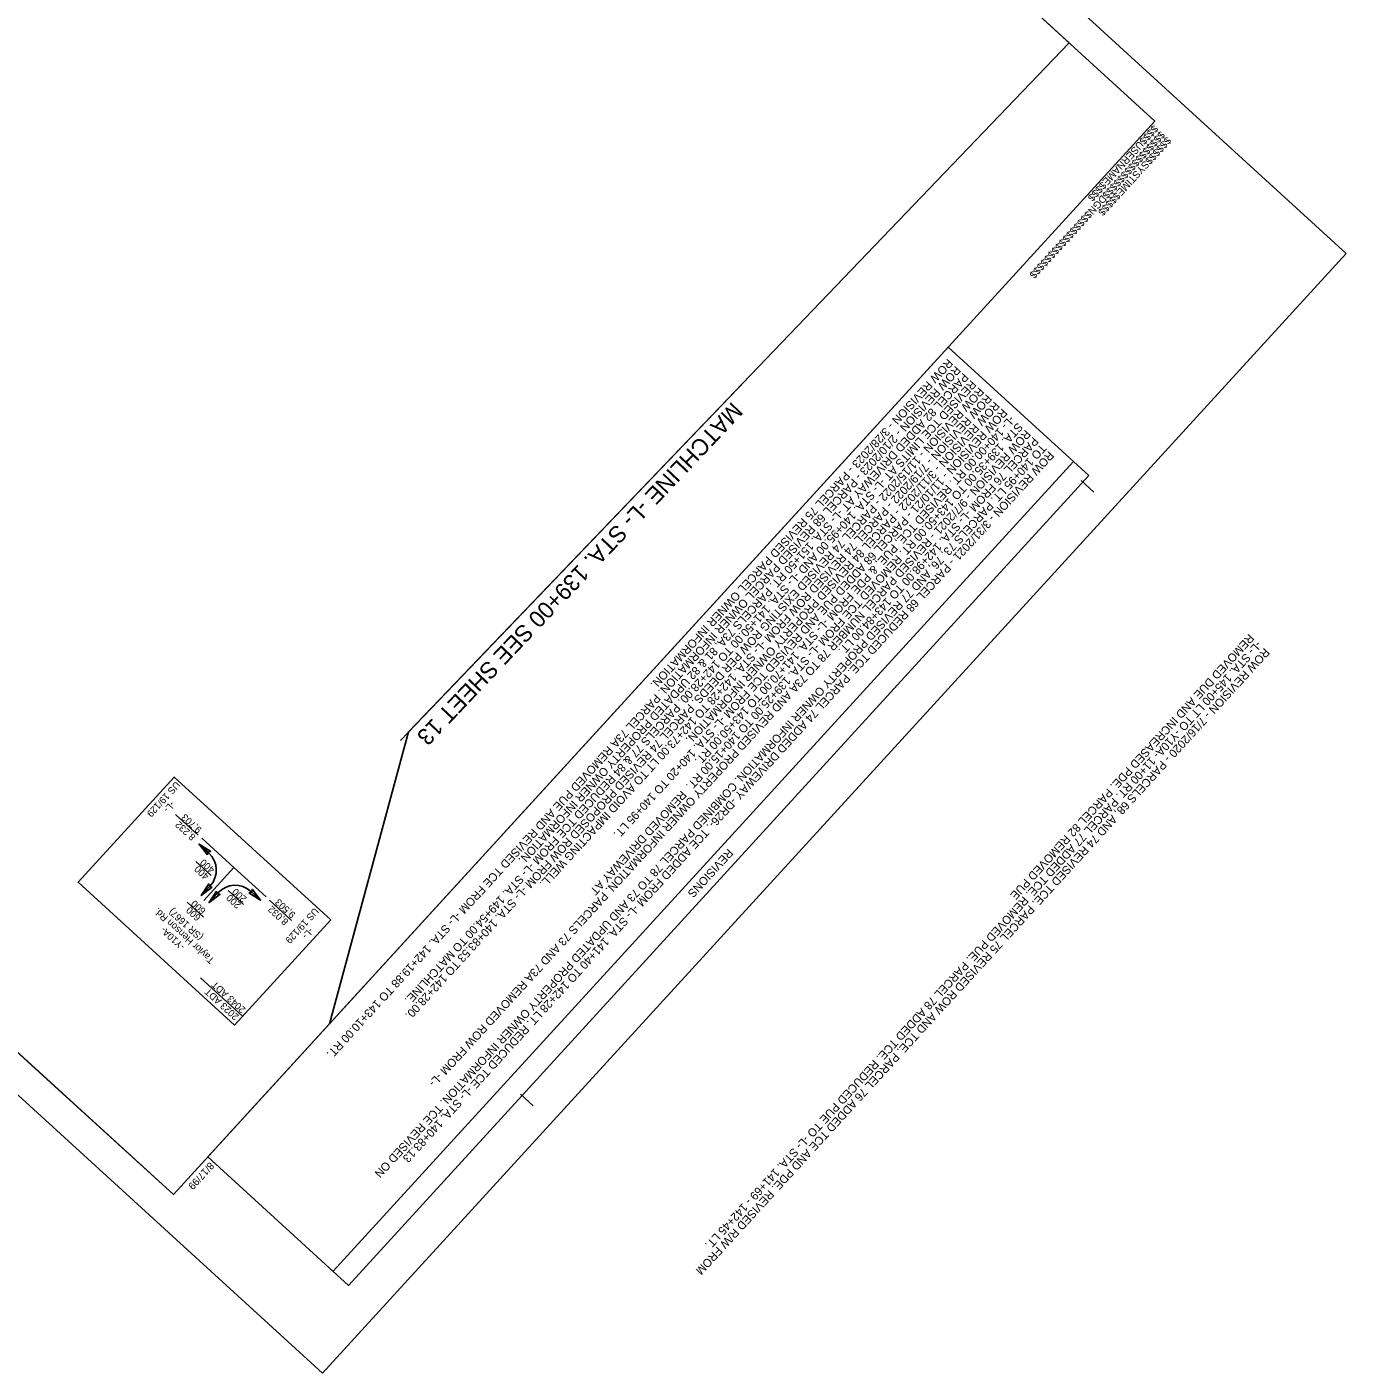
# Model space of a CAD drawing. Extents: x 475722 to 477703, y 499689 to 501633.
# Drawn here: x 476751 to 477703, y 499689 to 500661 of the extents above; entities that cross this region are included whole.
import ezdxf

# ---------------------------------------------------------------- set-up
doc = ezdxf.new("R2010")
doc.units = 0
for name, color, linetype in [('Matchline', 7, 'Continuous'), ('Matchline Text', 7, 'Continuous'), ('Prop DSN Text', 7, 'Continuous'), ('Prop Grid Mask', 7, 'Continuous'), ('Prop PHM Traffic Signal CELL', 7, 'Continuous'), ('Sheet Block Revision CELL', 7, 'Continuous'), ('Sheet Clip Boundary CELL', 7, 'Continuous'), ('Sheet Plan CELL', 7, 'Continuous'), ('Sheet Plot Border Outside CELL', 7, 'Continuous')]:
    doc.layers.add(name, color=color, linetype=linetype)

msp = doc.modelspace()

# ---------------------------------------------------------------- linework, layer by layer
at = {"layer": 'Matchline'}
msp.add_line((477269.58, 500406.16), (477020.46, 500146.28), dxfattribs=at)
at = {"layer": 'Prop DSN Text'}
for p, q in [((476878.68, 500030.7), (476900.34, 500054.4)), ((476876.81, 500034.23), (476883.24, 500041.25)), ((476882.34, 500029.15), (476888.77, 500036.18))]:
    msp.add_line(p, q, dxfattribs=at)
for points in [[(476881.33, 500063.57), (476875.17, 500071.39), (476883.62, 500066.07), (476881.49, 500065.6)], [(476884.63, 500040.39), (476876.81, 500034.23), (476882.13, 500042.68), (476882.6, 500040.55)], [(476911.17, 500036.29), (476919.52, 500030.86), (476913.46, 500038.8), (476913.18, 500036.64)], [(476887.79, 500037.5), (476882.36, 500029.15), (476890.3, 500035.21), (476888.14, 500035.49)]]:
    msp.add_lwpolyline(points, close=True, dxfattribs=at)
for centre, start, end in [((476870.87, 500052.58), 317.53481, 47.53479), ((476901.17, 500024.89), 47.62497, 137.62496)]:
    msp.add_arc(centre, 16.77, start, end, dxfattribs=at)
at = {"layer": 'Prop Grid Mask'}
msp.add_lwpolyline([(476900.81, 499940.64), (476787.89, 500043.82), (476857.32, 500119.8), (476970.24, 500016.62)], close=True, dxfattribs=at)
at = {"layer": 'Prop PHM Traffic Signal CELL'}
for p, q in [((476858.2, 500092.71), (476874.54, 500077.78)), ((476882.13, 500065.01), (476875.1, 500071.44)), ((476877.13, 500075.61), (476900.34, 500054.4)), ((476872.83, 500058.94), (476884.01, 500048.73)), ((476923.55, 500033.2), (476900.34, 500054.4)), ((476866.56, 500029.43), (476878.44, 500018.57)), ((476907.18, 500027.88), (476896.15, 500037.95)), ((476919.51, 500030.85), (476912.48, 500037.28)), ((476941.96, 500016.29), (476925.94, 500030.92)), ((476876.25, 499974.73), (476906.41, 499947.17))]:
    msp.add_line(p, q, dxfattribs=at)
at = {"layer": 'Sheet Block Revision CELL'}
msp.add_line((477506.17, 500347.75), (476971.88, 499763.02), dxfattribs=at)
msp.add_lwpolyline([(477517.42, 500337.46), (476983.13, 499752.76), (476881.48, 499845.57), (477415.77, 500430.27)], close=True, dxfattribs=at)
at = {"layer": 'Sheet Clip Boundary CELL'}
msp.add_lwpolyline([(475896.94, 500695.24), (476776.38, 499891.66), (476856.61, 499818.34), (476969.21, 499941.58), (477026.31, 500152.38), (477503.19, 500649.86), (476731.13, 501355.34), (476672.99, 501291.71), (476544.91, 501408.73), (475869.73, 500955.21), (476014.01, 500823.37)], close=True, dxfattribs=at)
at = {"layer": 'Sheet Plan CELL'}
for p, q in [((477564.89, 500593.48), (477564.89, 500593.48)), ((477521.05, 500325.38), (477511.83, 500333.83)), ((477116.34, 499882.45), (477107.08, 499890.87)), ((476856.61, 499818.34), (476856.61, 499818.34))]:
    msp.add_line(p, q, dxfattribs=at)
msp.add_lwpolyline([(475749.25, 500830.21), (476856.61, 499818.34), (477564.89, 500593.48), (476457.56, 501605.32)], close=True, dxfattribs=at)
at = {"layer": 'Sheet Plot Border Outside CELL'}
msp.add_lwpolyline([(477702.99, 500497.79), (476460.19, 501633.41), (475721.55, 500825.06), (476964.34, 499689.44)], close=True, dxfattribs=at)

# ---------------------------------------------------------------- texts
at = {"layer": 'Matchline Text'}
msp.add_text('MATCHLINE -L- STA. 139+00 SEE SHEET 13', height=12, rotation=226.58871, dxfattribs=at).set_placement((477259.86, 500391.23))
at = {"layer": 'Prop PHM Traffic Signal CELL'}
for s, rotation, p in [('US 19/129', 227.57996, (476858.36, 500117.07)), ('-L-', 227.57996, (476854.7, 500102.78)), ('8,232', 137.57984, (476873.13, 500077.09)), ('9,703', 137.57984, (476877.51, 500082.35)), ('400', 137.57984, (476886.9, 500053.5)), ('400', 137.57984, (476882.82, 500048.76)), ('200', 137.57993, (476910.07, 500032.37)), ('600', 137.57984, (476880.44, 500023.82)), ('200', 137.57993, (476905.88, 500027.98)), ('9,503', 137.57993, (476945.17, 500021.02)), ('Taylor Henson Rd. ', 137.57984, (476886.63, 499988.12)), ('(SR 1667)', 137.57984, (476878.52, 500004.92)), ('600', 137.57984, (476876.86, 500019.04)), ('8,032', 137.57993, (476940.12, 500015.92)), ('US 19/129', 227.57996, (476958.43, 500025.77)), ('-Y10A-', 137.57984, (476865.39, 499998.13)), ('-L-', 227.57996, (476954.76, 500011.48)), ('2043 ADT', 137.57984, (476909.19, 499952.49)), ('2023 ADT', 137.57984, (476904.28, 499947.39))]:
    msp.add_text(s, height=5, rotation=rotation, dxfattribs=at).set_placement(p)
at = {"layer": 'Sheet Block Revision CELL'}
for s, p in [('ROW REVISION - 3/28/2023 - PARCEL 75 REVISED PARCEL OWNER INFORMATION. ', (477415.4, 500422.28)), ('ROW REVISION - 2/10/2023 - PARCEL 68 REVISED PARCEL OWNER INFORMATION. PARCEL 73A REMOVED PUE AND REVISED TCE FROM -L- STA. 142+19.88 TO 143+10.00 RT. ', (477421.01, 500417.15)), ('PARCEL 82 ADDED DRIVEWAY AT -L- STA. 151+50 RT. PARCELS 73A, 81 & 82 UPDATED PROPERTY OWNER INFORMATION. ', (477426.63, 500412.02)), ('REVISED TCE LIMITS AT -L- STA. 140+95.00 AND -L- STA. 141+50.00 TO 142+28.00. PARCELS 77 & 84 REDUCED TCE FROM -L- STA. 149+54.00 TO MATCHLINE. ', (477432.24, 500406.89)), ('ROW REVISION - 11/15/2022 - PARCEL 74 REVISED EXISTING ROW PER DEEDS. PARCEL 74 REVISED PROPOSED ROW FROM -L- STA. 140+83.53 TO 142+28.00. ', (477437.86, 500401.76)), ('ROW REVISION - 7/19/2022 - PARCEL 74 REVISED ROW FROM -L- STA. 142+28 TO 142+73.00 LT TO AVOID IMPACTING WELL. ', (477443.47, 500396.63)), ('ROW REVISION - 3/11/2022 - PARCEL 84 REVISED PROPERTY OWNER INFORMATION.', (477449.09, 500391.5)), ('ROW REVISION - 11/10/21 - PARCEL 68 ADDED PUE AND REVISED TCE FROM -L- STA. 140+20 TO 140+95 LT. ', (477454.7, 500386.37)), ('-L- 140+00.00 RT. REVISED TCE, PUE, & PDE FROM -L- STA. 141+70.00 TO 143+50.00 RT. ', (477460.32, 500381.24)), ('ROW REVISION - 9/7/2021 - REVISED PARCEL NUMBER 78 TO 73A AND REVISED PROPERTY OWNER INFORMATION. PARCELS 73 AND 73A REMOVED ROW FROM -L- ', (477471.55, 500370.98)), ('STA. 139+35.00 TO 143+50.00 RT. REMOVED TCE FROM -L- STA. 139+25.00 TO 140+15.00 RT.  REMOVED DRIVEWAY AT ', (477465.93, 500376.11)), ('PARCEL 76 FROM -L- STA. 142+98.00 TO 143+84.00 LT. ', (477477.16, 500365.84)), ('TO 140+95 LT. PARCELS 73, 76, AND 77 REVISED PROPERTY OWNER INFORMATION. COMBINED PARCEL 78 TO 73 AND UPDATED PROPERTY OWNER INFORMATION. TCE REVISED ON ', (477482.78, 500360.71)), ('ROW REVISION - 3/31/2021 - PARCEL 68 REDUCED TCE. PARCEL 74 ADDED DRIVEWAY -DR26-. TCE ADDED FROM -L- STA. 141+40 TO 142+28 LT. REDUCED TCE -L- STA. 140+83.13 ', (477488.39, 500355.58)), ('-L- STA. 145+00 LT TO -Y10A- 11+00 RT. PARCEL 77 ADDED TCE. REMOVED PUE. PARCEL 78 ADDED TCE. REDUCED PUE TO -L- STA. 141+69 - 142+45 LT. ', (477638.4, 500218.51)), ('REMOVED DUE AND INCREASED PDE. PARCEL 82 REMOVED PUE', (477632.79, 500223.64)), ('ROW REVISION - 7/16/2020 - PARCELS 68, AND 74 REVISED TCE. PARCEL 75 REVISED ROW AND TCE. PARCEL 76 ADDED TCE AND PDE. REVISED R/W FROM', (477644.02, 500213.38)), ('REVISIONS', (477256.86, 500068.52))]:
    msp.add_text(s, height=6, rotation=227.57996, dxfattribs=at).set_placement(p)
at = {"layer": 'Sheet Plan CELL'}
for s, p in [('$$$$$$$$$$$$$$$$DGN$$$$$$$$$$$$$$$$', (477568.94, 500586.58)), ('$$$$USERNAME$$$$', (477564.1, 500590.99)), ('$$$$$$SYSTIME$$$$$', (477573.44, 500582.5)), ('8/17/99', (476882.75, 499842.17))]:
    msp.add_text(s, height=5.25, rotation=227.57997, dxfattribs=at).set_placement(p)

doc.saveas('drawing.dxf')
